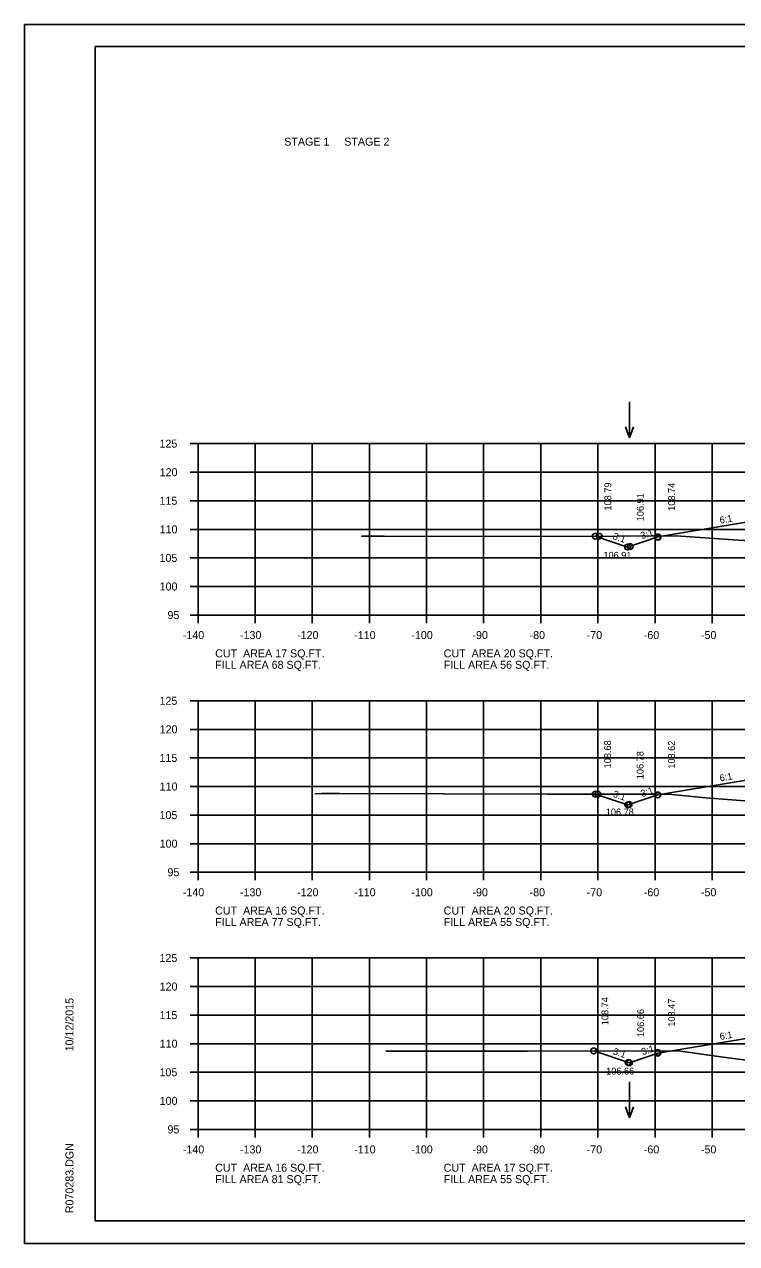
# Model space of a CAD drawing. Extents: x 1175611 to 1176402, y -433344 to -416213.
# Drawn here: x 1175610.6 to 1175735.3, y -423956.7 to -423743.3 of the extents above; entities that cross this region are included whole.
import ezdxf

# ---------------------------------------------------------------- set-up
doc = ezdxf.new("R2010")
doc.units = 0
for name, color, linetype in [('Default', 7, 'Continuous'), ('R_Axis', 7, 'Continuous'), ('R_Axis Annot', 7, 'Continuous'), ('R_Border', 7, 'Continuous'), ('R_Exist Surface', 7, 'Continuous'), ('R_Fin Surface', 7, 'Continuous'), ('R_Grid', 7, 'Continuous'), ('R_No Plot', 7, 'Continuous'), ('R_Water Annot', 7, 'Continuous'), ('R_Xsect Elev', 7, 'Continuous'), ('R_Xsect Slope', 7, 'Continuous')]:
    doc.layers.add(name, color=color, linetype=linetype)

msp = doc.modelspace()

# ---------------------------------------------------------------- linework, layer by layer
at = {"layer": 'R_Axis'}
for p, q in [((1175639.57, -423816.68), (1175640.97, -423816.68)), ((1175640.97, -423846.68), (1175640.97, -423816.68)), ((1175639.57, -423821.68), (1175640.97, -423821.68)), ((1175639.57, -423826.68), (1175640.97, -423826.68)), ((1175639.57, -423831.68), (1175640.97, -423831.68)), ((1175639.57, -423836.68), (1175640.97, -423836.68)), ((1175639.57, -423841.68), (1175640.97, -423841.68)), ((1175639.57, -423846.68), (1175640.97, -423846.68)), ((1175640.97, -423846.68), (1175920.97, -423846.68)), ((1175640.97, -423848.08), (1175640.97, -423846.68)), ((1175650.97, -423848.08), (1175650.97, -423846.68)), ((1175660.97, -423848.08), (1175660.97, -423846.68)), ((1175670.97, -423848.08), (1175670.97, -423846.68)), ((1175680.97, -423848.08), (1175680.97, -423846.68)), ((1175690.97, -423848.08), (1175690.97, -423846.68)), ((1175700.97, -423848.08), (1175700.97, -423846.68)), ((1175710.97, -423848.08), (1175710.97, -423846.68)), ((1175720.97, -423848.08), (1175720.97, -423846.68)), ((1175730.97, -423848.08), (1175730.97, -423846.68)), ((1175639.57, -423861.68), (1175640.97, -423861.68)), ((1175640.97, -423891.68), (1175640.97, -423861.68)), ((1175639.57, -423866.68), (1175640.97, -423866.68)), ((1175639.57, -423871.68), (1175640.97, -423871.68)), ((1175639.57, -423876.68), (1175640.97, -423876.68)), ((1175639.57, -423881.68), (1175640.97, -423881.68)), ((1175639.57, -423886.68), (1175640.97, -423886.68)), ((1175639.57, -423891.68), (1175640.97, -423891.68)), ((1175640.97, -423891.68), (1175920.97, -423891.68)), ((1175640.97, -423893.08), (1175640.97, -423891.68)), ((1175650.97, -423893.08), (1175650.97, -423891.68)), ((1175660.97, -423893.08), (1175660.97, -423891.68)), ((1175670.97, -423893.08), (1175670.97, -423891.68)), ((1175680.97, -423893.08), (1175680.97, -423891.68)), ((1175690.97, -423893.08), (1175690.97, -423891.68)), ((1175700.97, -423893.08), (1175700.97, -423891.68)), ((1175710.97, -423893.08), (1175710.97, -423891.68)), ((1175720.97, -423893.08), (1175720.97, -423891.68)), ((1175730.97, -423893.08), (1175730.97, -423891.68)), ((1175639.57, -423906.68), (1175640.97, -423906.68)), ((1175640.97, -423936.68), (1175640.97, -423906.68)), ((1175639.57, -423911.68), (1175640.97, -423911.68)), ((1175639.57, -423916.68), (1175640.97, -423916.68)), ((1175639.57, -423921.68), (1175640.97, -423921.68)), ((1175639.57, -423926.68), (1175640.97, -423926.68)), ((1175639.57, -423931.68), (1175640.97, -423931.68)), ((1175639.57, -423936.68), (1175640.97, -423936.68)), ((1175640.97, -423936.68), (1175920.97, -423936.68)), ((1175640.97, -423938.08), (1175640.97, -423936.68)), ((1175650.97, -423938.08), (1175650.97, -423936.68)), ((1175660.97, -423938.08), (1175660.97, -423936.68)), ((1175670.97, -423938.08), (1175670.97, -423936.68)), ((1175680.97, -423938.08), (1175680.97, -423936.68)), ((1175690.97, -423938.08), (1175690.97, -423936.68)), ((1175700.97, -423938.08), (1175700.97, -423936.68)), ((1175710.97, -423938.08), (1175710.97, -423936.68)), ((1175720.97, -423938.08), (1175720.97, -423936.68)), ((1175730.97, -423938.08), (1175730.97, -423936.68))]:
    msp.add_line(p, q, dxfattribs=at)
at = {"layer": 'R_Border'}
for p, q in [((1175622.97, -423747.22), (1175939.15, -423747.22)), ((1175622.97, -423952.68), (1175622.97, -423747.22)), ((1175622.97, -423952.68), (1175622.97, -423952.68)), ((1175939.15, -423952.68), (1175622.97, -423952.68))]:
    msp.add_line(p, q, dxfattribs=at)
at = {"layer": 'R_Exist Surface'}
for points in [[(1175669.58, -423832.89), (1175672, -423832.89), (1175673.56, -423832.89), (1175704, -423832.91), (1175724.67, -423832.83), (1175734.73, -423833.53), (1175744.22, -423834.08)], [(1175661.43, -423877.96), (1175662.61, -423877.9), (1175665.72, -423877.9), (1175702.16, -423877.99), (1175723.36, -423878.01), (1175729.88, -423878.67), (1175738.95, -423879.38)], [(1175673.86, -423923.01), (1175675.23, -423923.01), (1175678.24, -423923.01), (1175698.66, -423922.97), (1175725.01, -423922.91), (1175732.89, -423924.01), (1175738.25, -423924.75)]]:
    msp.add_lwpolyline(points, dxfattribs=at)
at = {"layer": 'R_Fin Surface'}
for points in [[(1175710.5, -423832.88), (1175716.17, -423834.77), (1175721.47, -423833), (1175735.2, -423830.72), (1175743.47, -423829.34), (1175749.47, -423829.1), (1175751.47, -423829.06), (1175780.97, -423828.47), (1175810.47, -423829.06), (1175812.47, -423829.1), (1175818.47, -423829.34), (1175826.75, -423830.72), (1175840.47, -423833), (1175845.29, -423834.61), (1175851.38, -423832.58)], [(1175710.51, -423878), (1175716.2, -423879.9), (1175721.47, -423878.14), (1175735.2, -423875.85), (1175743.47, -423874.47), (1175749.47, -423874.23), (1175751.47, -423874.19), (1175780.97, -423873.6), (1175810.47, -423874.19), (1175812.47, -423874.23), (1175818.47, -423874.47), (1175826.75, -423875.85), (1175840.47, -423878.14), (1175845.31, -423879.75), (1175851.73, -423877.61)], [(1175710.25, -423922.94), (1175716.49, -423925.02), (1175721.47, -423923.36), (1175735.2, -423921.07), (1175743.47, -423919.69), (1175749.47, -423919.45), (1175751.47, -423919.41), (1175780.97, -423918.82), (1175810.47, -423919.41), (1175812.47, -423919.45), (1175818.47, -423919.69), (1175826.75, -423921.07), (1175840.47, -423923.36), (1175845.09, -423924.9), (1175851.11, -423922.89)]]:
    msp.add_lwpolyline(points, dxfattribs=at)
at = {"layer": 'R_Grid'}
for p, q in [((1175640.97, -423816.68), (1175920.97, -423816.68)), ((1175640.97, -423846.68), (1175640.97, -423816.68)), ((1175650.97, -423846.68), (1175650.97, -423816.68)), ((1175660.97, -423846.68), (1175660.97, -423816.68)), ((1175670.97, -423846.68), (1175670.97, -423816.68)), ((1175680.97, -423846.68), (1175680.97, -423816.68)), ((1175690.97, -423846.68), (1175690.97, -423816.68)), ((1175700.97, -423846.68), (1175700.97, -423816.68)), ((1175710.97, -423846.68), (1175710.97, -423816.68)), ((1175720.97, -423846.68), (1175720.97, -423816.68)), ((1175730.97, -423846.68), (1175730.97, -423816.68)), ((1175640.97, -423821.68), (1175920.97, -423821.68)), ((1175640.97, -423826.68), (1175920.97, -423826.68)), ((1175640.97, -423831.68), (1175920.97, -423831.68)), ((1175640.97, -423836.68), (1175920.97, -423836.68)), ((1175640.97, -423841.68), (1175920.97, -423841.68)), ((1175640.97, -423846.68), (1175920.97, -423846.68)), ((1175640.97, -423861.68), (1175920.97, -423861.68)), ((1175640.97, -423891.68), (1175640.97, -423861.68)), ((1175650.97, -423891.68), (1175650.97, -423861.68)), ((1175660.97, -423891.68), (1175660.97, -423861.68)), ((1175670.97, -423891.68), (1175670.97, -423861.68)), ((1175680.97, -423891.68), (1175680.97, -423861.68)), ((1175690.97, -423891.68), (1175690.97, -423861.68)), ((1175700.97, -423891.68), (1175700.97, -423861.68)), ((1175710.97, -423891.68), (1175710.97, -423861.68)), ((1175720.97, -423891.68), (1175720.97, -423861.68)), ((1175730.97, -423891.68), (1175730.97, -423861.68)), ((1175640.97, -423866.68), (1175920.97, -423866.68)), ((1175640.97, -423871.68), (1175920.97, -423871.68)), ((1175640.97, -423876.68), (1175920.97, -423876.68)), ((1175640.97, -423881.68), (1175920.97, -423881.68)), ((1175640.97, -423886.68), (1175920.97, -423886.68)), ((1175640.97, -423891.68), (1175920.97, -423891.68)), ((1175640.97, -423906.68), (1175920.97, -423906.68)), ((1175640.97, -423936.68), (1175640.97, -423906.68)), ((1175650.97, -423936.68), (1175650.97, -423906.68)), ((1175660.97, -423936.68), (1175660.97, -423906.68)), ((1175670.97, -423936.68), (1175670.97, -423906.68)), ((1175680.97, -423936.68), (1175680.97, -423906.68)), ((1175690.97, -423936.68), (1175690.97, -423906.68)), ((1175700.97, -423936.68), (1175700.97, -423906.68)), ((1175710.97, -423936.68), (1175710.97, -423906.68)), ((1175720.97, -423936.68), (1175720.97, -423906.68)), ((1175730.97, -423936.68), (1175730.97, -423906.68)), ((1175640.97, -423911.68), (1175920.97, -423911.68)), ((1175640.97, -423916.68), (1175920.97, -423916.68)), ((1175640.97, -423921.68), (1175920.97, -423921.68)), ((1175640.97, -423926.68), (1175920.97, -423926.68)), ((1175640.97, -423931.68), (1175920.97, -423931.68)), ((1175640.97, -423936.68), (1175920.97, -423936.68))]:
    msp.add_line(p, q, dxfattribs=at)
at = {"layer": 'R_No Plot'}
for p, q in [((1175610.57, -423743.32), (1175943.91, -423743.32)), ((1175610.57, -423956.66), (1175943.91, -423956.66))]:
    msp.add_line(p, q, dxfattribs=at)
msp.add_lwpolyline([(1175610.57, -423743.32), (1175943.91, -423743.32), (1175943.91, -423956.66), (1175610.57, -423956.66)], close=True, dxfattribs=at)
for centre in [(1175710.5, -423832.88), (1175710.5, -423832.88), (1175711.2, -423832.88), (1175721.47, -423833), (1175721.47, -423833.08), (1175716.17, -423834.77), (1175716.63, -423834.69), (1175710.51, -423878), (1175710.51, -423878), (1175710.97, -423878), (1175721.47, -423878.14), (1175721.47, -423878.15), (1175716.2, -423879.9), (1175716.44, -423879.82), (1175710.22, -423922.94), (1175710.25, -423922.94), (1175710.25, -423922.94), (1175721.47, -423923.21), (1175721.47, -423923.36), (1175716.25, -423924.95), (1175716.49, -423925.02)]:
    msp.add_circle(centre, 0.5, dxfattribs=at)
at = {"layer": 'R_Water Annot'}
for p, q in [((1175716.53, -423809.36), (1175716.53, -423815.65)), ((1175716.53, -423815.65), (1175715.83, -423813.72)), ((1175716.53, -423815.65), (1175717.23, -423813.72)), ((1175716.53, -423928.37), (1175716.53, -423934.66)), ((1175716.53, -423934.66), (1175715.83, -423932.73)), ((1175716.53, -423934.66), (1175717.23, -423932.73))]:
    msp.add_line(p, q, dxfattribs=at)

# ---------------------------------------------------------------- texts
at = {"layer": 'Default'}
for s, p in [('STAGE 1     STAGE 2', (1175656.06, -423764.54)), ('CUT  AREA 17 SQ.FT.', (1175643.97, -423854.08)), ('CUT  AREA 20 SQ.FT.', (1175683.97, -423854.08)), ('FILL AREA 68 SQ.FT.', (1175643.97, -423856.08)), ('FILL AREA 56 SQ.FT.', (1175683.97, -423856.08)), ('CUT  AREA 16 SQ.FT.', (1175643.97, -423899.08)), ('FILL AREA 77 SQ.FT.', (1175643.97, -423901.08)), ('CUT  AREA 20 SQ.FT.', (1175683.97, -423899.08)), ('FILL AREA 55 SQ.FT.', (1175683.97, -423901.08)), ('CUT  AREA 16 SQ.FT.', (1175643.97, -423944.08)), ('CUT  AREA 17 SQ.FT.', (1175683.97, -423944.08)), ('FILL AREA 81 SQ.FT.', (1175643.97, -423946.08)), ('FILL AREA 55 SQ.FT.', (1175683.97, -423946.08))]:
    msp.add_text(s, height=1.4, dxfattribs=at).set_placement(p)
at = {"layer": 'R_Axis Annot'}
for s, p in [('125', (1175634.22, -423817.38)), ('120', (1175634.25, -423822.38)), ('115', (1175634.22, -423827.38)), ('110', (1175634.25, -423832.38)), ('105', (1175634.22, -423837.38)), ('100', (1175634.25, -423842.38)), ('95', (1175635.62, -423847.38)), ('-140', (1175638.31, -423850.88)), ('-130', (1175648.31, -423850.88)), ('-120', (1175658.31, -423850.88)), ('-110', (1175668.31, -423850.88)), ('-100', (1175678.31, -423850.88)), ('-90', (1175689.01, -423850.88)), ('-80', (1175699.01, -423850.88)), ('-70', (1175709.01, -423850.88)), ('-60', (1175719.01, -423850.88)), ('-50', (1175729.01, -423850.88)), ('125', (1175634.22, -423862.38)), ('120', (1175634.25, -423867.38)), ('115', (1175634.22, -423872.38)), ('110', (1175634.25, -423877.38)), ('105', (1175634.22, -423882.38)), ('100', (1175634.25, -423887.38)), ('95', (1175635.62, -423892.38)), ('-140', (1175638.31, -423895.88)), ('-130', (1175648.31, -423895.88)), ('-120', (1175658.31, -423895.88)), ('-110', (1175668.31, -423895.88)), ('-100', (1175678.31, -423895.88)), ('-90', (1175689.01, -423895.88)), ('-80', (1175699.01, -423895.88)), ('-70', (1175709.01, -423895.88)), ('-60', (1175719.01, -423895.88)), ('-50', (1175729.01, -423895.88)), ('125', (1175634.22, -423907.38)), ('120', (1175634.25, -423912.38)), ('115', (1175634.22, -423917.38)), ('110', (1175634.25, -423922.38)), ('105', (1175634.22, -423927.38)), ('100', (1175634.25, -423932.38)), ('95', (1175635.62, -423937.38)), ('-140', (1175638.31, -423940.88)), ('-130', (1175648.31, -423940.88)), ('-120', (1175658.31, -423940.88)), ('-110', (1175668.31, -423940.88)), ('-100', (1175678.31, -423940.88)), ('-90', (1175689.01, -423940.88)), ('-80', (1175699.01, -423940.88)), ('-70', (1175709.01, -423940.88)), ('-60', (1175719.01, -423940.88)), ('-50', (1175729.01, -423940.88))]:
    msp.add_text(s, height=1.4, dxfattribs=at).set_placement(p)
at = {"layer": 'R_Border'}
for s, p in [('10/12/2015', (1175619.16, -423923.04)), ('R070283.DGN', (1175619.16, -423951.35))]:
    msp.add_text(s, height=1.4, rotation=90, dxfattribs=at).set_placement(p)
at = {"layer": 'R_Xsect Elev'}
for s, p in [('108.79', (1175713.32, -423828.39)), ('108.74', (1175724.47, -423828.44)), ('106.91', (1175718.98, -423830.27)), ('108.68', (1175713.27, -423873.5)), ('108.62', (1175724.47, -423873.56)), ('106.78', (1175718.96, -423875.4)), ('108.74', (1175712.81, -423918.44)), ('108.47', (1175724.47, -423918.71)), ('106.66', (1175719.05, -423920.52))]:
    msp.add_text(s, height=1.2, rotation=90, dxfattribs=at).set_placement(p)
for s, p in [('106.91', (1175711.94, -423836.82)), ('106.78', (1175712.35, -423881.73)), ('106.66', (1175712.42, -423927.08))]:
    msp.add_text(s, height=1.2, dxfattribs=at).set_placement(p)
at = {"layer": 'R_Xsect Slope'}
for s, rotation, p in [('6:1', 9.4623, (1175732.39, -423830.68)), ('3:1', 341.5651, (1175713.49, -423833.35)), ('3:1', 18.4349, (1175718.66, -423833.41)), ('6:1', 9.4623, (1175732.39, -423875.81)), ('3:1', 341.5651, (1175713.51, -423878.47)), ('3:1', 18.4349, (1175718.68, -423878.54)), ('6:1', 9.4623, (1175732.39, -423921.03)), ('3:1', 341.5651, (1175713.53, -423923.51)), ('3:1', 18.4349, (1175718.82, -423923.71))]:
    msp.add_text(s, height=1.2, rotation=rotation, dxfattribs=at).set_placement(p)

doc.saveas('drawing.dxf')
